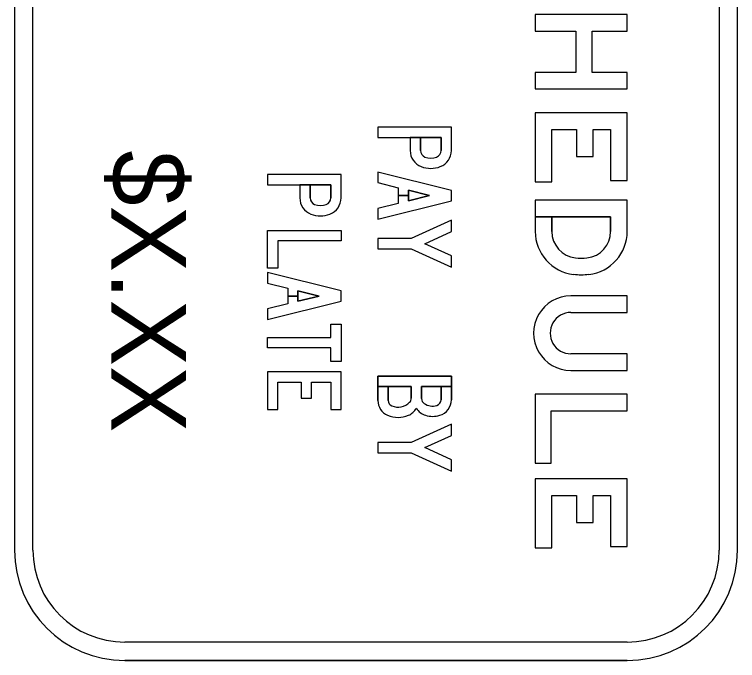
# Model space of a CAD drawing. Extents: x 46672 to 47298, y 5424 to 5742.
# Drawn here: x 47141.98 to 47166.75, y 5553.65 to 5575.78 of the extents above; entities that cross this region are included whole.
import ezdxf

# ---------------------------------------------------------------- set-up
doc = ezdxf.new("R2010")
doc.units = 0
doc.layers.add('SignPanel', color=7, linetype='Continuous')

msp = doc.modelspace()

# ---------------------------------------------------------------- linework, layer by layer
at = {"layer": 'SignPanel'}
for p, q in [((47141.977, 5598.386), (47141.977, 5557.433)), ((47142.607, 5557.433), (47142.607, 5598.386)), ((47166.12, 5598.386), (47166.12, 5557.433)), ((47166.75, 5557.433), (47166.75, 5598.386)), ((47156.946, 5571.123), (47156.946, 5571.921)), ((47153.166, 5569.499), (47153.166, 5570.297)), ((47159.819, 5568.852), (47159.819, 5568.353)), ((47159.819, 5568.852), (47159.819, 5568.353)), ((47160.386, 5568.852), (47160.386, 5568.353)), ((47162.97, 5564.158), (47161.04, 5564.158)), ((47162.97, 5564.158), (47161.04, 5564.158)), ((47162.97, 5564.158), (47161.04, 5564.158)), ((47162.97, 5554.282), (47145.758, 5554.282)), ((47162.97, 5553.652), (47145.758, 5553.652)), ((47145.758, 5553.652), (47162.97, 5553.652))]:
    msp.add_line(p, q, dxfattribs=at)
for points in [[(47161.772, 5573.798), (47161.772, 5575.216), (47162.97, 5575.216), (47162.97, 5575.783), (47159.819, 5575.783), (47159.819, 5575.216), (47161.205, 5575.216), (47161.205, 5573.798), (47159.819, 5573.798), (47159.819, 5573.231), (47162.97, 5573.231), (47162.97, 5573.798)], [(47161.772, 5573.798), (47161.772, 5575.216), (47162.97, 5575.216), (47162.97, 5575.783), (47159.819, 5575.783), (47159.819, 5575.216), (47161.205, 5575.216), (47161.205, 5573.798), (47159.819, 5573.798), (47159.819, 5573.231), (47162.97, 5573.231), (47162.97, 5573.798)], [(47161.772, 5573.798), (47161.772, 5575.216), (47162.97, 5575.216), (47162.97, 5575.783), (47159.819, 5575.783), (47159.819, 5575.216), (47161.205, 5575.216), (47161.205, 5573.798), (47159.819, 5573.798), (47159.819, 5573.231), (47162.97, 5573.231), (47162.97, 5573.798)], [(47160.386, 5570.049), (47160.386, 5571.845), (47161.234, 5571.845), (47161.234, 5570.915), (47161.801, 5570.915), (47161.801, 5571.845), (47162.402, 5571.845), (47162.402, 5570.096), (47162.97, 5570.096), (47162.97, 5572.412), (47159.819, 5572.412), (47159.819, 5570.049)], [(47160.386, 5570.049), (47160.386, 5571.845), (47161.234, 5571.845), (47161.234, 5570.915), (47161.801, 5570.915), (47161.801, 5571.845), (47162.402, 5571.845), (47162.402, 5570.096), (47162.97, 5570.096), (47162.97, 5572.412), (47159.819, 5572.412), (47159.819, 5570.049)], [(47160.386, 5570.049), (47160.386, 5571.845), (47161.234, 5571.845), (47161.234, 5570.915), (47161.801, 5570.915), (47161.801, 5571.845), (47162.402, 5571.845), (47162.402, 5570.096), (47162.97, 5570.096), (47162.97, 5572.412), (47159.819, 5572.412), (47159.819, 5570.049)], [(47155.119, 5569.85), (47155.119, 5569.311), (47154.426, 5569.137), (47154.426, 5568.774), (47156.946, 5569.404), (47156.946, 5569.757), (47154.426, 5570.387), (47154.426, 5570.023)], [(47155.472, 5569.58), (47155.472, 5569.762), (47156.197, 5569.58), (47155.472, 5569.399), (47155.472, 5569.58), (47155.119, 5569.58), (47155.119, 5569.311), (47154.426, 5569.137), (47154.426, 5568.774), (47156.946, 5569.404), (47156.946, 5569.757), (47154.426, 5570.387), (47154.426, 5570.023), (47155.119, 5569.85), (47155.119, 5569.58)], [(47155.472, 5569.58), (47155.472, 5569.762), (47156.197, 5569.58), (47155.472, 5569.399), (47155.472, 5569.58), (47155.119, 5569.58), (47155.119, 5569.311), (47154.426, 5569.137), (47154.426, 5568.774), (47156.946, 5569.404), (47156.946, 5569.757), (47154.426, 5570.387), (47154.426, 5570.023), (47155.119, 5569.85), (47155.119, 5569.58)], [(47155.472, 5569.399), (47156.197, 5569.58), (47155.472, 5569.762)], [(47155.573, 5568.109), (47154.426, 5568.109), (47154.426, 5567.756), (47155.573, 5567.756), (47156.946, 5567.126), (47156.946, 5567.514), (47156.034, 5567.932), (47156.946, 5568.351), (47156.946, 5568.739)], [(47155.573, 5568.109), (47154.426, 5568.109), (47154.426, 5567.756), (47155.573, 5567.756), (47156.946, 5567.126), (47156.946, 5567.514), (47156.034, 5567.932), (47156.946, 5568.351), (47156.946, 5568.739)], [(47155.573, 5568.109), (47154.426, 5568.109), (47154.426, 5567.756), (47155.573, 5567.756), (47156.946, 5567.126), (47156.946, 5567.514), (47156.034, 5567.932), (47156.946, 5568.351), (47156.946, 5568.739)], [(47153.166, 5568.381), (47153.166, 5568.028), (47150.998, 5568.028), (47150.998, 5567.096), (47150.646, 5567.096), (47150.646, 5568.381)], [(47153.166, 5568.381), (47153.166, 5568.028), (47150.998, 5568.028), (47150.998, 5567.096), (47150.646, 5567.096), (47150.646, 5568.381)], [(47153.166, 5568.381), (47153.166, 5568.028), (47150.998, 5568.028), (47150.998, 5567.096), (47150.646, 5567.096), (47150.646, 5568.381)], [(47151.339, 5566.408), (47151.339, 5565.869), (47150.646, 5565.695), (47150.646, 5565.332), (47153.166, 5565.962), (47153.166, 5566.315), (47150.646, 5566.945), (47150.646, 5566.581)], [(47151.691, 5566.138), (47151.691, 5566.319), (47152.417, 5566.138), (47151.691, 5565.957), (47151.691, 5566.138), (47151.339, 5566.138), (47151.339, 5565.869), (47150.646, 5565.695), (47150.646, 5565.332), (47153.166, 5565.962), (47153.166, 5566.315), (47150.646, 5566.945), (47150.646, 5566.581), (47151.339, 5566.408), (47151.339, 5566.138)], [(47151.691, 5566.138), (47151.691, 5566.319), (47152.417, 5566.138), (47151.691, 5565.957), (47151.691, 5566.138), (47151.339, 5566.138), (47151.339, 5565.869), (47150.646, 5565.695), (47150.646, 5565.332), (47153.166, 5565.962), (47153.166, 5566.315), (47150.646, 5566.945), (47150.646, 5566.581), (47151.339, 5566.408), (47151.339, 5566.138)], [(47151.691, 5565.957), (47152.417, 5566.138), (47151.691, 5566.319)], [(47152.813, 5564.714), (47152.813, 5565.18), (47153.166, 5565.18), (47153.166, 5563.895), (47152.813, 5563.895), (47152.813, 5564.361), (47150.646, 5564.361), (47150.646, 5564.714)], [(47152.813, 5564.714), (47152.813, 5565.18), (47153.166, 5565.18), (47153.166, 5563.895), (47152.813, 5563.895), (47152.813, 5564.361), (47150.646, 5564.361), (47150.646, 5564.714)], [(47152.813, 5564.714), (47152.813, 5565.18), (47153.166, 5565.18), (47153.166, 5563.895), (47152.813, 5563.895), (47152.813, 5564.361), (47150.646, 5564.361), (47150.646, 5564.714)], [(47150.998, 5563.189), (47151.805, 5563.189), (47151.805, 5562.637), (47152.158, 5562.637), (47152.158, 5563.189), (47152.813, 5563.189), (47152.813, 5562.257), (47153.166, 5562.257), (47153.166, 5563.542), (47150.646, 5563.542), (47150.646, 5562.257), (47150.998, 5562.257)], [(47150.998, 5563.189), (47151.805, 5563.189), (47151.805, 5562.637), (47152.158, 5562.637), (47152.158, 5563.189), (47152.813, 5563.189), (47152.813, 5562.257), (47153.166, 5562.257), (47153.166, 5563.542), (47150.646, 5563.542), (47150.646, 5562.257), (47150.998, 5562.257)], [(47150.998, 5563.189), (47151.805, 5563.189), (47151.805, 5562.637), (47152.158, 5562.637), (47152.158, 5563.189), (47152.813, 5563.189), (47152.813, 5562.257), (47153.166, 5562.257), (47153.166, 5563.542), (47150.646, 5563.542), (47150.646, 5562.257), (47150.998, 5562.257)], [(47159.819, 5560.409), (47160.37, 5560.409), (47160.37, 5562.205), (47162.97, 5562.205), (47162.97, 5562.772), (47159.819, 5562.772)], [(47159.819, 5560.409), (47160.37, 5560.409), (47160.37, 5562.205), (47162.97, 5562.205), (47162.97, 5562.772), (47159.819, 5562.772)], [(47159.819, 5560.409), (47160.37, 5560.409), (47160.37, 5562.205), (47162.97, 5562.205), (47162.97, 5562.772), (47159.819, 5562.772)], [(47155.573, 5561.123), (47154.426, 5561.123), (47154.426, 5560.77), (47155.573, 5560.77), (47156.946, 5560.14), (47156.946, 5560.528), (47156.034, 5560.946), (47156.946, 5561.365), (47156.946, 5561.753)], [(47155.573, 5561.123), (47154.426, 5561.123), (47154.426, 5560.77), (47155.573, 5560.77), (47156.946, 5560.14), (47156.946, 5560.528), (47156.034, 5560.946), (47156.946, 5561.365), (47156.946, 5561.753)], [(47155.573, 5561.123), (47154.426, 5561.123), (47154.426, 5560.77), (47155.573, 5560.77), (47156.946, 5560.14), (47156.946, 5560.528), (47156.034, 5560.946), (47156.946, 5561.365), (47156.946, 5561.753)], [(47160.386, 5557.511), (47160.386, 5559.306), (47161.234, 5559.306), (47161.234, 5558.377), (47161.801, 5558.377), (47161.801, 5559.306), (47162.402, 5559.306), (47162.402, 5557.558), (47162.97, 5557.558), (47162.97, 5559.873), (47159.819, 5559.873), (47159.819, 5557.511)], [(47160.386, 5557.511), (47160.386, 5559.306), (47161.234, 5559.306), (47161.234, 5558.377), (47161.801, 5558.377), (47161.801, 5559.306), (47162.402, 5559.306), (47162.402, 5557.558), (47162.97, 5557.558), (47162.97, 5559.873), (47159.819, 5559.873), (47159.819, 5557.511)], [(47160.386, 5557.511), (47160.386, 5559.306), (47161.234, 5559.306), (47161.234, 5558.377), (47161.801, 5558.377), (47161.801, 5559.306), (47162.402, 5559.306), (47162.402, 5557.558), (47162.97, 5557.558), (47162.97, 5559.873), (47159.819, 5559.873), (47159.819, 5557.511)]]:
    msp.add_lwpolyline(points, close=True, dxfattribs=at)
for points in [[(47156.946, 5571.921), (47154.426, 5571.921), (47154.426, 5571.568), (47155.535, 5571.568), (47155.535, 5571.123)], [(47156.946, 5571.123), (47156.946, 5571.921), (47154.426, 5571.921), (47154.426, 5571.568), (47156.593, 5571.568), (47156.593, 5571.123)], [(47156.946, 5571.123), (47156.946, 5571.921), (47154.426, 5571.921), (47154.426, 5571.568), (47156.593, 5571.568), (47156.593, 5571.123)], [(47155.888, 5571.123), (47155.888, 5571.568), (47155.535, 5571.568), (47155.535, 5571.123)], [(47155.888, 5571.123), (47155.888, 5571.568), (47155.535, 5571.568), (47155.535, 5571.123)], [(47156.593, 5571.123), (47156.593, 5571.568), (47155.888, 5571.568), (47155.888, 5571.123)], [(47153.166, 5570.297), (47150.646, 5570.297), (47150.646, 5569.944), (47151.755, 5569.944), (47151.755, 5569.499)], [(47153.166, 5569.499), (47153.166, 5570.297), (47150.646, 5570.297), (47150.646, 5569.944), (47152.813, 5569.944), (47152.813, 5569.499)], [(47153.166, 5569.499), (47153.166, 5570.297), (47150.646, 5570.297), (47150.646, 5569.944), (47152.813, 5569.944), (47152.813, 5569.499)], [(47152.107, 5569.499), (47152.107, 5569.944), (47151.755, 5569.944), (47151.755, 5569.499)], [(47152.107, 5569.499), (47152.107, 5569.944), (47151.755, 5569.944), (47151.755, 5569.499)], [(47152.813, 5569.499), (47152.813, 5569.944), (47152.107, 5569.944), (47152.107, 5569.499)], [(47162.97, 5568.353), (47162.97, 5569.419), (47159.819, 5569.419), (47159.819, 5568.353)], [(47162.97, 5568.353), (47162.97, 5569.419), (47159.819, 5569.419), (47159.819, 5568.852), (47162.402, 5568.852), (47162.402, 5568.353)], [(47162.97, 5568.353), (47162.97, 5569.419), (47159.819, 5569.419), (47159.819, 5568.852), (47162.402, 5568.852), (47162.402, 5568.353)], [(47160.386, 5568.353), (47160.386, 5568.852), (47159.819, 5568.852)], [(47160.386, 5568.353), (47160.386, 5568.852), (47159.819, 5568.852)], [(47162.402, 5568.353), (47162.402, 5568.852), (47160.386, 5568.852)], [(47161.04, 5565.576), (47162.97, 5565.576), (47162.97, 5566.143), (47161.04, 5566.143)], [(47161.04, 5565.576), (47162.97, 5565.576), (47162.97, 5566.143), (47161.04, 5566.143)], [(47161.04, 5565.576), (47162.97, 5565.576), (47162.97, 5566.143), (47161.04, 5566.143)], [(47161.04, 5563.591), (47162.97, 5563.591), (47162.97, 5564.158)], [(47161.04, 5563.591), (47162.97, 5563.591), (47162.97, 5564.158)], [(47161.04, 5563.591), (47162.97, 5563.591), (47162.97, 5564.158)], [(47156.946, 5562.585), (47156.946, 5563.391), (47154.426, 5563.391), (47154.426, 5562.562)], [(47155.573, 5562.64), (47155.573, 5563.038), (47154.426, 5563.038), (47154.426, 5563.391), (47156.946, 5563.391), (47156.946, 5563.038), (47155.926, 5563.038), (47155.926, 5562.626)], [(47155.573, 5562.64), (47155.573, 5563.038), (47154.426, 5563.038), (47154.426, 5563.391), (47156.946, 5563.391), (47156.946, 5563.038), (47155.926, 5563.038), (47155.926, 5562.626)], [(47154.426, 5562.562), (47154.426, 5563.038), (47154.779, 5563.038), (47154.779, 5562.562)], [(47154.426, 5562.562), (47154.426, 5563.038), (47154.779, 5563.038), (47154.779, 5562.562)], [(47154.779, 5562.562), (47154.779, 5563.038), (47155.573, 5563.038), (47155.573, 5562.64)], [(47155.926, 5562.626), (47155.926, 5563.038), (47156.593, 5563.038), (47156.593, 5562.585)], [(47156.593, 5562.585), (47156.593, 5563.038), (47156.946, 5563.038), (47156.946, 5562.585)], [(47156.593, 5562.585), (47156.593, 5563.038), (47156.946, 5563.038), (47156.946, 5562.585)]]:
    msp.add_lwpolyline(points, dxfattribs=at)
for centre, radius, start, end in [((47154.98, 5562.562), 0.554, 180, 246.8676), ((47154.98, 5562.562), 0.554, 180, 246.8676), ((47154.98, 5562.562), 0.554, 180, 246.8676), ((47154.98, 5562.562), 0.202, 180, 246.8676), ((47154.98, 5562.562), 0.202, 180, 246.8676), ((47154.98, 5562.562), 0.202, 180, 246.8676), ((47155.371, 5562.64), 0.202, 315.5847, 0), ((47155.371, 5562.64), 0.202, 315.5847, 0), ((47155.371, 5562.64), 0.202, 315.5847, 0), ((47156.127, 5562.626), 0.202, 180, 235.9442), ((47156.127, 5562.626), 0.202, 180, 235.9442), ((47156.127, 5562.626), 0.202, 180, 235.9442), ((47156.392, 5562.585), 0.202, 286.2602, 0), ((47156.392, 5562.585), 0.202, 286.2602, 0), ((47156.392, 5562.585), 0.202, 286.2602, 0), ((47156.392, 5562.585), 0.554, 286.2602, 0), ((47156.392, 5562.585), 0.554, 286.2602, 0), ((47156.392, 5562.585), 0.554, 286.2602, 0), ((47155.119, 5562.887), 0.554, 246.8676, 315.5847), ((47155.119, 5562.887), 0.554, 246.8676, 315.5847), ((47155.119, 5562.887), 0.554, 246.8676, 315.5847), ((47155.258, 5562.562), 0.554, 293.1324, 331.0715), ((47155.258, 5562.562), 0.554, 293.1324, 331.0715), ((47155.258, 5562.562), 0.554, 293.1324, 331.0715), ((47156.215, 5562.585), 0.554, 211.5648, 253.7398), ((47156.215, 5562.585), 0.554, 211.5648, 253.7398), ((47156.215, 5562.585), 0.554, 211.5648, 253.7398), ((47156.304, 5562.887), 0.517, 235.9442, 286.2602), ((47156.304, 5562.887), 0.517, 235.9442, 286.2602), ((47156.304, 5562.887), 0.517, 235.9442, 286.2602), ((47155.119, 5562.887), 0.907, 246.8676, 293.1324), ((47155.119, 5562.887), 0.907, 246.8676, 293.1324), ((47155.119, 5562.887), 0.907, 246.8676, 293.1324), ((47156.304, 5562.887), 0.87, 253.7398, 286.2602), ((47156.304, 5562.887), 0.87, 253.7398, 286.2602), ((47156.304, 5562.887), 0.87, 253.7398, 286.2602), ((47145.758, 5557.433), 3.78, 180, 270), ((47145.758, 5557.433), 3.78, 180, 270), ((47145.758, 5557.433), 3.15, 180, 270), ((47162.97, 5557.433), 3.78, 270, 0), ((47162.97, 5557.433), 3.78, 270, 0), ((47162.97, 5557.433), 3.15, 270, 0)]:
    msp.add_arc(centre, radius, start, end, dxfattribs=at)
for centre, major_axis, ratio, start_param, end_param in [((47156.127, 5571.123), (0.592, 0), 0.999996, 3.141593, 4.344121), ((47156.127, 5571.123), (0.592, 0), 0.999996, 3.141593, 4.344121), ((47156.127, 5571.123), (0.592, 0), 0.999996, 3.141593, 4.344121), ((47156.127, 5571.123), (0.239, 0), 0.999996, 3.141593, 4.344121), ((47156.127, 5571.123), (0.239, 0), 0.999996, 3.141593, 4.344121), ((47156.127, 5571.123), (0.239, 0), 0.999996, 3.141593, 4.344121), ((47156.354, 5571.123), (0.239, 0), 0.999996, 5.080657, 6.283185), ((47156.354, 5571.123), (0.239, 0), 0.999996, 5.080657, 6.283185), ((47156.354, 5571.123), (0.239, 0), 0.999996, 5.080657, 6.283185), ((47156.354, 5571.123), (0.592, 0), 0.999996, 5.080657, 6.283185), ((47156.354, 5571.123), (0.592, 0), 0.999996, 5.080657, 6.283185), ((47156.354, 5571.123), (0.592, 0), 0.999996, 5.080657, 6.283185), ((47156.241, 5571.417), (0.554, 0), 0.999996, 4.344121, 5.080657), ((47156.241, 5571.417), (0.554, 0), 0.999996, 4.344121, 5.080657), ((47156.241, 5571.417), (0.554, 0), 0.999996, 4.344121, 5.080657), ((47156.241, 5571.417), (0.907, 0), 0.999996, 4.344121, 5.080657), ((47156.241, 5571.417), (0.907, 0), 0.999996, 4.344121, 5.080657), ((47156.241, 5571.417), (0.907, 0), 0.999996, 4.344121, 5.080657), ((47152.347, 5569.499), (0.592, 0), 0.999996, 3.141593, 4.344121), ((47152.347, 5569.499), (0.592, 0), 0.999996, 3.141593, 4.344121), ((47152.347, 5569.499), (0.592, 0), 0.999996, 3.141593, 4.344121), ((47152.347, 5569.499), (0.239, 0), 0.999996, 3.141593, 4.344121), ((47152.347, 5569.499), (0.239, 0), 0.999996, 3.141593, 4.344121), ((47152.347, 5569.499), (0.239, 0), 0.999996, 3.141593, 4.344121), ((47152.574, 5569.499), (0.239, 0), 0.999996, 5.080657, 6.283185), ((47152.574, 5569.499), (0.239, 0), 0.999996, 5.080657, 6.283185), ((47152.574, 5569.499), (0.239, 0), 0.999996, 5.080657, 6.283185), ((47152.574, 5569.499), (0.592, 0), 0.999996, 5.080657, 6.283185), ((47152.574, 5569.499), (0.592, 0), 0.999996, 5.080657, 6.283185), ((47152.574, 5569.499), (0.592, 0), 0.999996, 5.080657, 6.283185), ((47152.46, 5569.793), (0.554, 0), 0.999996, 4.344121, 5.080657), ((47152.46, 5569.793), (0.554, 0), 0.999996, 4.344121, 5.080657), ((47152.46, 5569.793), (0.554, 0), 0.999996, 4.344121, 5.080657), ((47152.46, 5569.793), (0.907, 0), 0.999996, 4.344121, 5.080657), ((47152.46, 5569.793), (0.907, 0), 0.999996, 4.344121, 5.080657), ((47152.46, 5569.793), (0.907, 0), 0.999996, 4.344121, 5.080657), ((47161.3, 5568.353), (1.481, 0), 0.999995, 3.141593, 4.598938), ((47161.3, 5568.353), (1.481, 0), 0.999995, 3.141593, 4.598938), ((47161.3, 5568.353), (1.481, 0), 0.999995, 3.141593, 4.598938), ((47161.3, 5568.353), (0.914, 0), 0.999995, 3.141593, 4.598938), ((47161.3, 5568.353), (0.914, 0), 0.999995, 3.141593, 4.598938), ((47161.3, 5568.353), (0.914, 0), 0.999995, 3.141593, 4.598938), ((47161.489, 5568.353), (0.914, 0), 0.999995, 4.82584, 6.283185), ((47161.489, 5568.353), (0.914, 0), 0.999995, 4.82584, 6.283185), ((47161.489, 5568.353), (0.914, 0), 0.999995, 4.82584, 6.283185), ((47161.489, 5568.353), (1.481, 0), 0.999995, 4.82584, 6.283185), ((47161.489, 5568.353), (1.481, 0), 0.999995, 4.82584, 6.283185), ((47161.489, 5568.353), (1.481, 0), 0.999995, 4.82584, 6.283185), ((47161.394, 5569.183), (1.748, 0), 0.999995, 4.598938, 4.82584), ((47161.394, 5569.183), (1.748, 0), 0.999995, 4.598938, 4.82584), ((47161.394, 5569.183), (1.748, 0), 0.999995, 4.598938, 4.82584), ((47161.394, 5569.183), (2.316, 0), 0.999995, 4.598938, 4.82584), ((47161.394, 5569.183), (2.316, 0), 0.999995, 4.598938, 4.82584), ((47161.394, 5569.183), (2.316, 0), 0.999995, 4.598938, 4.82584), ((47161.04, 5564.867), (1.276, 0), 0.999995, 1.570796, 4.712389), ((47161.04, 5564.867), (1.276, 0), 0.999995, 1.570796, 4.712389), ((47161.04, 5564.867), (1.276, 0), 0.999995, 1.570796, 4.712389), ((47161.04, 5564.867), (0.709, 0), 0.999995, 1.570796, 4.712389), ((47161.04, 5564.867), (0.709, 0), 0.999995, 1.570796, 4.712389), ((47161.04, 5564.867), (0.709, 0), 0.999995, 1.570796, 4.712389)]:
    msp.add_ellipse(centre, major_axis=major_axis, ratio=ratio, start_param=start_param, end_param=end_param, dxfattribs=at)

# ---------------------------------------------------------------- texts
msp.add_text('$X.XX', height=2.5485, rotation=270, dxfattribs=at).set_placement((47145.301, 5571.13))

doc.saveas('drawing.dxf')
